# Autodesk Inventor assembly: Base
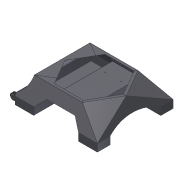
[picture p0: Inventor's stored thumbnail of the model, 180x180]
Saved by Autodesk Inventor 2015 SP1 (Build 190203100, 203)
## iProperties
Category: Mechanical Engineering Drawing and Design - CADD
Manager: Fábio Ricardo de Oliveira Souza
Company: SENAI - Serviço Nacional de Aprendizagem Industrial
Created: 2011-06
Part Number: Base
Document SubType Name: Weldment
Designer: Guilherme Augusto Franco de Souza
Engineer: George Geraldo de Oliveia Silva
Authority: Fábio Ricardo de Oliveira Soza
Weld Material: Welded Stainless Steel, 440C
Description: Sub-assembly
Subject: WorldSkill 2011 - London, England
Author: Guilherme Augusto Franco de Souza
Revision Number: 00
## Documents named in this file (13)
- E:\Visitor Experience Project\WSI2015 - Visitor Experience Project\#46- Sheet Metal Technology\01- 3D Models\Outodoor Heater\2- Assemblies\Base.iam
- E:\Visitor Experience Project\WSI2015 - Visitor Experience Project\#46- Sheet Metal Technology\01- 3D Models\Outodoor Heater\2- Assemblies\External base.iam
- E:\Visitor Experience Project\WSI2015 - Visitor Experience Project\#46- Sheet Metal Technology\01- 3D Models\Outodoor Heater\2- Assemblies\Internal base.iam
- E:\Visitor Experience Project\WSI2015 - Visitor Experience Project\#46- Sheet Metal Technology\01- 3D Models\Outodoor Heater\2- Assemblies\Outdoor Burner\Design Accelerator\Bolted Connection1.iam
- E:\Visitor Experience Project\WSI2015 - Visitor Experience Project\#46- Sheet Metal Technology\01- 3D Models\Outodoor Heater\2- Assemblies\Outdoor Burner\Design Accelerator\Bolted Connection2.iam
- E:\Visitor Experience Project\WSI2015 - Visitor Experience Project\#46- Sheet Metal Technology\01- 3D Models\Outodoor Heater\2- Assemblies\Outdoor Burner\Design Accelerator\Bolted Connection3.iam
- E:\Visitor Experience Project\WSI2015 - Visitor Experience Project\#46- Sheet Metal Technology\01- 3D Models\Outodoor Heater\2- Assemblies\Outdoor Burner\Design Accelerator\Bolted Connection4.iam
- E:\Visitor Experience Project\WSI2015 - Visitor Experience Project\#46- Sheet Metal Technology\01- 3D Models\Outodoor Heater\1- Parts\ISO_R 1051 - 4 x 8 x 3,5.ipt
- E:\Visitor Experience Project\WSI2015 - Visitor Experience Project\#46- Sheet Metal Technology\01- 3D Models\Outodoor Heater\2- Assemblies\Base\Design Accelerator\Bolted Connection1.iam
- E:\Visitor Experience Project\WSI2015 - Visitor Experience Project\#46- Sheet Metal Technology\01- 3D Models\Outodoor Heater\2- Assemblies\Base\Design Accelerator\Bolted Connection2.iam
- E:\Visitor Experience Project\WSI2015 - Visitor Experience Project\#46- Sheet Metal Technology\01- 3D Models\Outodoor Heater\2- Assemblies\Base\Design Accelerator\Bolted Connection3.iam
- E:\Visitor Experience Project\WSI2015 - Visitor Experience Project\#46- Sheet Metal Technology\01- 3D Models\Outodoor Heater\1- Parts\ISO_R 1051 - 3 x 8 x 3,741.ipt
- E:\Visitor Experience Project\WSI2015 - Visitor Experience Project\#46- Sheet Metal Technology\01- 3D Models\Outodoor Heater\2- Assemblies\Roller.iam
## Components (25 placed, 6 different names)
1. External base:1 [sub-assembly] — Flush:1, Mate:1, Mate:2, Insert:1, Insert:2, Insert:3, Insert:4, Insert:5, Insert:6, Insert:7, Insert:8, Insert:9, Insert:10, Insert:11, Insert:12, Insert:13, Insert:14, Mate:24, Mate:25, Mate:26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
2. Internal base:1 [sub-assembly] — Flush:1, Mate:1, Mate:2, Mate:17, Mate:18, Mate:19, Mate:20, Mate:21, Mate:22
3. Bolted Connection:1 [sub-assembly] — Mate:24, Mate:25
4. Bolted Connection:2 [sub-assembly] — Mate:26, Mate:27
5. Bolted Connection:3 [sub-assembly] — Mate:28, Mate:29
6. Bolted Connection:4 [sub-assembly] — Mate:30, Mate:31
7. ISO_R 1051 - 4 x 8 x 3,5:1 — Insert:1
8. ISO_R 1051 - 4 x 8 x 3,5:2 — Insert:2
9. ISO_R 1051 - 4 x 8 x 3,5:3 — Insert:4
10. ISO_R 1051 - 4 x 8 x 3,5:4 — Insert:3
11. ISO_R 1051 - 4 x 8 x 3,5:5 — Insert:7
12. ISO_R 1051 - 4 x 8 x 3,5:6 — Insert:8
13. ISO_R 1051 - 4 x 8 x 3,5:7 — Insert:9
14. ISO_R 1051 - 4 x 8 x 3,5:8 — Insert:10
15. ISO_R 1051 - 4 x 8 x 3,5:9 — Insert:5
16. ISO_R 1051 - 4 x 8 x 3,5:10 — Insert:6
17. Bolted Connection:5 [sub-assembly] — Mate:17, Mate:18
18. Bolted Connection:6 [sub-assembly] — Mate:19, Mate:20
19. Bolted Connection:7 [sub-assembly] — Mate:21, Mate:22
20. ISO_R 1051 - 3 x 8 x 3,741:1 — Insert:11
21. ISO_R 1051 - 3 x 8 x 3,741:2 — Insert:12
22. ISO_R 1051 - 3 x 8 x 3,741:3 — Insert:14
23. ISO_R 1051 - 3 x 8 x 3,741:4 — Insert:13
24. Roller:1 [sub-assembly] — Mate:28, Mate:29
25. Roller:2 [sub-assembly] — Mate:30, Mate:31
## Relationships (31: Mate 16, Insert 14, Flush 1)
- Flush:1: External base:1 ↔ Internal base:1
- Mate:1: External base:1 ↔ Internal base:1
- Mate:2: External base:1 ↔ Internal base:1
- Insert:1: External base:1 ↔ ISO_R 1051 - 4 x 8 x 3,5:1
- Insert:2: External base:1 ↔ ISO_R 1051 - 4 x 8 x 3,5:2
- Insert:3: External base:1 ↔ ISO_R 1051 - 4 x 8 x 3,5:4
- Insert:4: External base:1 ↔ ISO_R 1051 - 4 x 8 x 3,5:3
- Insert:5: External base:1 ↔ ISO_R 1051 - 4 x 8 x 3,5:9
- Insert:6: External base:1 ↔ ISO_R 1051 - 4 x 8 x 3,5:10
- Insert:7: External base:1 ↔ ISO_R 1051 - 4 x 8 x 3,5:5
- Insert:8: External base:1 ↔ ISO_R 1051 - 4 x 8 x 3,5:6
- Insert:9: External base:1 ↔ ISO_R 1051 - 4 x 8 x 3,5:7
- Insert:10: External base:1 ↔ ISO_R 1051 - 4 x 8 x 3,5:8
- Insert:11: External base:1 ↔ ISO_R 1051 - 3 x 8 x 3,741:1
- Insert:12: External base:1 ↔ ISO_R 1051 - 3 x 8 x 3,741:2
- Insert:13: External base:1 ↔ ISO_R 1051 - 3 x 8 x 3,741:4
- Insert:14: External base:1 ↔ ISO_R 1051 - 3 x 8 x 3,741:3
- Mate:17: Internal base:1 ↔ Bolted Connection:5
- Mate:18: Internal base:1 ↔ Bolted Connection:5
- Mate:19: Internal base:1 ↔ Bolted Connection:6
- Mate:20: Internal base:1 ↔ Bolted Connection:6
- Mate:21: Internal base:1 ↔ Bolted Connection:7
- Mate:22: Internal base:1 ↔ Bolted Connection:7
- Mate:24: External base:1 ↔ Bolted Connection:1
- Mate:25: External base:1 ↔ Bolted Connection:1
- Mate:26: External base:1 ↔ Bolted Connection:2
- Mate:27: External base:1 ↔ Bolted Connection:2
- Mate:28: Bolted Connection:3 ↔ Roller:1
- Mate:29: Bolted Connection:3 ↔ Roller:1
- Mate:30: Bolted Connection:4 ↔ Roller:2
- Mate:31: Bolted Connection:4 ↔ Roller:2
## Named parameters: d44_d18 = 0, d46_d42 = 0, d47_d43 = 0
